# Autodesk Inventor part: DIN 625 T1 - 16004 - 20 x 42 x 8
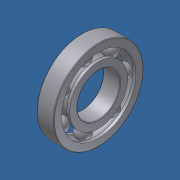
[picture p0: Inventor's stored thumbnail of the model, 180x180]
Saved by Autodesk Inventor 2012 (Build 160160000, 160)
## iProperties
Created: 2006-02
Part Number: DIN 625 T1 - 16004 - 20 x 42 x 8
Material: Steel, Mild
Description: Deep Groove Ball Bearing
Document SubType Name: Modeling
Standard: DIN 625 T1
Designer: Andy Moles
Standards Organization: DIN
Language: en-US
Size Designation: 16004 - 20 x 42 x 8
Categories: <MemberInstance><Categories><Category DisplayName="Shaft Parts" InternalName="7f7aeb1f-a693-4053-b835-cee3144e0d98" Mnemonic="SHFT"><Category DisplayName="Beari
Density: 7.86 g/cm^3
Mass: 44.1545 g
Surface Area: 55.9541 cm^2
Volume: 5.61762 cm^3
Author: Andy Moles
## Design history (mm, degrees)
revolve "Body" stored, may be unused: angle "d7" = 90 deg
revolve "Ball" stored, may be unused: angle "d9" = 90 deg
pattern_circular "Balls" dims angle "d2" = 360 deg
body "Solid1"
sketch "Sketch" dims "d3" = 6.5934 (= DDB)
  geometry: L1 (0.703, 15.5)-(7.297, 15.5); L2 (4, 15.5)-(4, 12.203); L3 (1.316, 13.586)-(0, 13.586); L4 (0, 10)-(8, 10); L5 (1.316, 17.414)-(0, 17.414); L6 (0, 21)-(8, 21); L7 (8, 17.414)-(8, 21); L8 (6.684, 17.414)-(8, 17.414); L9 (8, 10)-(8, 13.586); L10 (6.684, 13.586)-(8, 13.586); L11 (4, 15.5)-(4, 18.797); L12 (-1.5, 0)-(19.5, 0) reference; L13 (0, -0.85)-(0, 18.05) reference
  constraints: 22 end point, 4 point on line, 3 parallel, 3 perpendicular, 3 symmetric about line, 1 midpoint, 12 other
  dimensions: "d8" = 20 diameter of L4 L12 (= WD); "d10" = 27.172 diameter of L3 L12 (= KID1); "d12" = 34.828 diameter of L5 L12 (= KAD1); "d13" = 42 diameter of L6 L12 (= BD); "d14" = 31 diameter of L2.start L12 (= DDA); "d15" = 8 distance between parallel lines of L13 L9 (= KB)
fillet "Fillet1" dims "d0" = 0.3 (= KRS)
other parameters: "WD" = 20 [user parameter; used in 2 equation terms], "BD" = 42 [user parameter; used in 2 equation terms], "KB" = 8 [user parameter; used in 1 equation term], "KRS" = 0.3 [user parameter; used in 1 equation term], "KID1" = 27.172 [user parameter; used in 1 equation term], "KAD1" = 34.828 [user parameter; used in 1 equation term], "DDA" = 31 [user parameter; used in 2 equation terms], "DDB" = 6.5934 [user parameter; used in 2 equation terms], "d4" = 0, "d5" = 0, "d6" = 0, "d16" = 0, "d17" = 0, "BC0" = 4050000 [user parameter], "BC" = 6890000 [user parameter], "BR" = 21 (= 0.5 x BD) [user parameter], "BBA" = 0 [user parameter]
